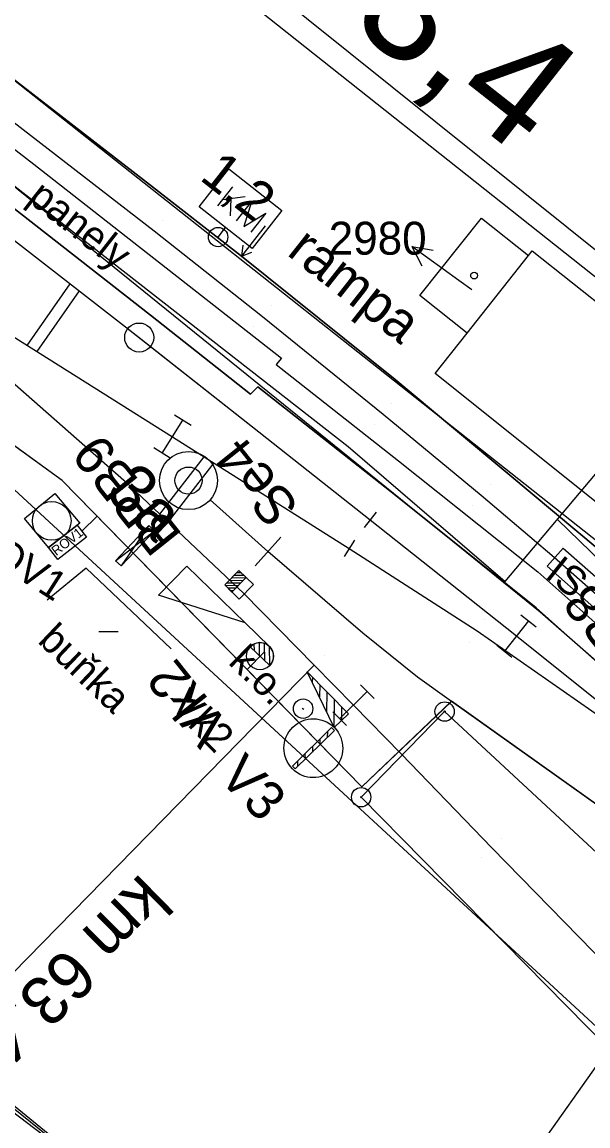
# Model space of a CAD drawing. Extents: x -620475 to -619963, y -1123010 to -1122510.
# Drawn here: x -620299.9 to -620270.7, y -1122722.8 to -1122665.8 of the extents above; entities that cross this region are included whole.
import ezdxf

# ---------------------------------------------------------------- set-up
doc = ezdxf.new("R2010")
doc.units = 0
for name, color, linetype in [('060601_EOV', 7, 'Continuous'), ('060604_ROZVODY_SEE', 7, 'Continuous'), ('CETIN', 7, 'Continuous'), ('HranDP', 7, 'Continuous'), ('Hranice parcel', 7, 'Continuous'), ('Parcelní čísla', 7, 'Continuous'), ('Pop  PČ popisy', 7, 'Continuous'), ('PS 06-14-01_trasa_sdělovací_nové', 7, 'Continuous'), ('SEE', 7, 'Continuous'), ('SSZT', 7, 'Continuous'), ('Vnitřní kresba', 7, 'Continuous'), ('Vrstva 1', 7, 'Continuous'), ('Vrstva 12', 7, 'Continuous'), ('Vrstva 16', 7, 'Continuous'), ('Vrstva 2', 7, 'Continuous'), ('Vrstva 23', 7, 'Continuous'), ('Vrstva 25', 7, 'Continuous'), ('Vrstva 27', 7, 'Continuous'), ('Vrstva 3', 7, 'Continuous'), ('Vrstva 4', 7, 'Continuous'), ('Vrstva 51', 7, 'Continuous'), ('Vrstva 59', 7, 'Continuous'), ('Vrstva 62', 7, 'Continuous'), ('Vrstva 7', 7, 'Continuous'), ('Věcná břemena k části', 7, 'Continuous'), ('Značky bodu BP', 7, 'Continuous'), ('Značky budov', 7, 'Continuous')]:
    doc.layers.add(name, color=color, linetype=linetype)

msp = doc.modelspace()

# ---------------------------------------------------------------- linework, layer by layer
at = {"layer": '060601_EOV'}
msp.add_lwpolyline([(-620235.16, -1122712.242), (-620240.174, -1122718.342), (-620243.025, -1122715.998), (-620248.321, -1122722.765), (-620259.889, -1122713.575), (-620277.713, -1122700.902), (-620282.346, -1122705.302), (-620297.82, -1122689.49), (-620304.222, -1122684.862), (-620310.815, -1122680.061), (-620322.228, -1122672.322), (-620343.182, -1122658.459), (-620368.499, -1122642.897), (-620385.559, -1122631.811)], dxfattribs=at)
at = {"layer": '060604_ROZVODY_SEE'}
msp.add_line((-620296.802, -1122692.105), (-620296.015, -1122691.335), dxfattribs=at)
msp.add_lwpolyline([(-620243.025, -1122715.998), (-620248.321, -1122722.765), (-620259.889, -1122713.575), (-620277.713, -1122700.902), (-620282.346, -1122705.302), (-620297.82, -1122689.49), (-620304.222, -1122684.862), (-620310.815, -1122680.061), (-620316.822, -1122675.988), (-620322.228, -1122672.322), (-620326.634, -1122669.408), (-620343.182, -1122658.459), (-620368.499, -1122642.897), (-620385.559, -1122631.811)], dxfattribs=at)
msp.add_lwpolyline([(-620298.522, -1122692.948), (-620297.044, -1122691.795), (-620296.56, -1122692.415), (-620298.039, -1122693.568)], close=True, dxfattribs=at)
at = {"layer": 'CETIN'}
for points in [[(-620398.075, -1122646.118), (-620362.48, -1122674.84), (-620281.95, -1122736.09)], [(-620281.95, -1122736.09), (-620279.78, -1122731.91), (-620278.12, -1122730.04), (-620275.23, -1122726.8), (-620267.96, -1122716.51), (-620253.8, -1122706.08), (-620234.3, -1122721.82), (-620227.04, -1122727.67)]]:
    msp.add_lwpolyline(points, dxfattribs=at)
at = {"layer": 'HranDP'}
for points in [[(-620296.23, -1122649.3), (-620298.73, -1122654.76), (-620265, -1122681.82), (-620263.22, -1122682.69), (-620260.55, -1122682.94), (-620253.83, -1122686.12), (-620245.73, -1122689.53), (-620242.51, -1122691.82), (-620225.75, -1122705.35), (-620226.24, -1122705.93)], [(-620310.57, -1122708.76), (-620307.94, -1122715.53), (-620278.65, -1122739.48), (-620275.74, -1122741.01)]]:
    msp.add_lwpolyline(points, dxfattribs=at)
at = {"layer": 'Hranice parcel'}
for points in [[(-620296.23, -1122649.3), (-620298.73, -1122654.76), (-620265, -1122681.82), (-620263.22, -1122682.69), (-620260.55, -1122682.94), (-620253.83, -1122686.12), (-620245.73, -1122689.53), (-620242.51, -1122691.82), (-620225.75, -1122705.35), (-620226.24, -1122705.93)], [(-620302.66, -1122666.96), (-620267.81, -1122694.49), (-620266.86, -1122693.31), (-620261.82, -1122686.93), (-620261.22, -1122686.17), (-620299.15, -1122656.1), (-620301.83, -1122654.06), (-620305.28, -1122659.46), (-620299.56, -1122663.58), (-620302.66, -1122666.96)], [(-620264.06, -1122726.18), (-620263.28, -1122725.23), (-620282.38, -1122705.84), (-620278.07, -1122701.42), (-620246.12, -1122731.05)], [(-620310.57, -1122708.76), (-620307.94, -1122715.53), (-620278.65, -1122739.48), (-620275.74, -1122741.01)]]:
    msp.add_lwpolyline(points, dxfattribs=at)
at = {"layer": 'Pop  PČ popisy'}
for p, q in [((-620277.33, -1122679.17), (-620279.758, -1122677.406)), ((-620279.758, -1122677.406), (-620278.653, -1122677.59)), ((-620279.758, -1122677.406), (-620279.242, -1122678.4)), ((-620276.66, -1122679.65), (-620277.33, -1122679.17))]:
    msp.add_line(p, q, dxfattribs=at)
at = {"layer": 'PS 06-14-01_trasa_sdělovací_nové'}
msp.add_lwpolyline([(-620248.321, -1122722.765), (-620259.889, -1122713.575), (-620277.711, -1122700.887), (-620282.346, -1122705.302), (-620297.82, -1122689.49), (-620310.815, -1122680.061), (-620322.228, -1122672.322), (-620343.182, -1122658.459), (-620368.499, -1122642.897), (-620385.559, -1122631.811)], dxfattribs=at)
at = {"layer": 'SEE'}
msp.add_line((-620272.241, -1122691.503), (-620257.327, -1122706.026), dxfattribs=at)
for points in [[(-620340.053, -1122630.257), (-620307.038, -1122645.433), (-620304.995, -1122662.882), (-620304.721, -1122665.223), (-620302.66, -1122666.96), (-620305.446, -1122670.265), (-620283.044, -1122687.742), (-620274.947, -1122694.711), (-620269.357, -1122688.084), (-620267.489, -1122689.555)], [(-620244.518, -1122694.296), (-620246.547, -1122692.66), (-620267.469, -1122718.6), (-620268.222, -1122719.534), (-620284.407, -1122704.62), (-620304.333, -1122686.26), (-620309.55, -1122681.453), (-620327.714, -1122669.483), (-620362.834, -1122646.339), (-620385.658, -1122631.923)]]:
    msp.add_lwpolyline(points, dxfattribs=at)
at = {"layer": 'SSZT'}
msp.add_lwpolyline([(-620386.367, -1122632.734), (-620363.271, -1122647.563), (-620313.966, -1122679.218), (-620306.51, -1122669.289), (-620273.137, -1122696.274), (-620258.422, -1122709.142), (-620248.072, -1122696.094)], dxfattribs=at)
at = {"layer": 'Vnitřní kresba'}
for p, q in [((-620279.35, -1122679.94), (-620276.17, -1122675.94)), ((-620276.17, -1122675.94), (-620273.73, -1122677.87)), ((-620276.91, -1122681.88), (-620273.73, -1122677.87)), ((-620273.73, -1122677.87), (-620273.55, -1122677.64)), ((-620273.55, -1122677.64), (-620261.82, -1122686.93)), ((-620276.91, -1122681.88), (-620279.35, -1122679.94)), ((-620278.56, -1122683.97), (-620276.91, -1122681.88)), ((-620266.86, -1122693.31), (-620278.56, -1122683.97))]:
    msp.add_line(p, q, dxfattribs=at)
at = {"layer": 'Vrstva 1'}
for p, q in [((-620287.398, -1122698.346), (-620288.271, -1122699.248)), ((-620282.346, -1122705.302), (-620288.271, -1122699.248)), ((-620277.713, -1122700.902), (-620278.485, -1122701.635)), ((-620259.889, -1122713.575), (-620277.713, -1122700.902)), ((-620282.346, -1122705.302), (-620278.485, -1122701.635))]:
    msp.add_line(p, q, dxfattribs=at)
for points in [[(-620383.649, -1122629.627), (-620378.269, -1122633.015), (-620362.958, -1122642.66), (-620347.616, -1122652.305), (-620342.456, -1122655.575), (-620322.526, -1122668.083), (-620312.925, -1122674.13), (-620301.163, -1122681.549), (-620292.126, -1122687.227), (-620282.992, -1122692.997), (-620276.394, -1122697.25), (-620266.758, -1122703.956), (-620255.894, -1122712.191)], [(-620322.526, -1122668.083), (-620313.097, -1122674.436), (-620308.214, -1122678.053), (-620306.7, -1122679.227), (-620305.337, -1122680.296), (-620302.152, -1122682.886), (-620294.636, -1122689.472), (-620288.443, -1122695.324), (-620284.812, -1122699.019), (-620282.778, -1122701.089), (-620280.313, -1122703.598), (-620275.628, -1122708.447), (-620262.902, -1122721.469), (-620255.487, -1122728.261), (-620248.439, -1122734.187)], [(-620300.366, -1122670.953), (-620293.063, -1122676.601), (-620287.47, -1122681.018), (-620281.24, -1122686.066), (-620276.174, -1122690.251), (-620272.417, -1122693.451), (-620267.757, -1122697.544), (-620266.519, -1122698.689), (-620262.242, -1122702.65), (-620256.103, -1122708.562), (-620249.907, -1122714.621), (-620245.657, -1122718.815), (-620238.557, -1122725.547), (-620230.199, -1122732.623), (-620229.854, -1122732.906)], [(-620288.271, -1122699.248), (-620297.82, -1122689.49), (-620304.222, -1122684.862), (-620310.815, -1122680.061), (-620311.612, -1122679.521), (-620316.822, -1122675.988)], [(-620300.906, -1122676.615), (-620294.546, -1122681.556), (-620293.844, -1122682.108), (-620287.988, -1122686.712), (-620281.909, -1122691.52), (-620277.852, -1122694.735), (-620274.362, -1122697.517), (-620269.944, -1122701.034), (-620263.761, -1122705.928), (-620255.894, -1122712.191), (-620251.107, -1122715.999), (-620247.589, -1122718.79), (-620245.37, -1122720.556), (-620245.065, -1122720.798), (-620243.16, -1122722.318), (-620236.673, -1122727.474), (-620229.854, -1122732.906), (-620228.705, -1122733.823), (-620228.351, -1122734.106), (-620222.324, -1122738.923), (-620215.936, -1122744.099), (-620211.427, -1122747.773)], [(-620300.906, -1122676.615), (-620294.546, -1122681.556), (-620287.988, -1122686.712), (-620281.909, -1122691.52), (-620277.852, -1122694.735), (-620274.362, -1122697.517), (-620269.944, -1122701.034), (-620263.761, -1122705.928), (-620255.894, -1122712.191), (-620251.107, -1122715.999), (-620247.589, -1122718.79), (-620245.37, -1122720.556), (-620245.065, -1122720.798), (-620243.16, -1122722.318), (-620236.673, -1122727.474), (-620229.854, -1122732.906), (-620228.705, -1122733.823), (-620228.351, -1122734.106), (-620222.324, -1122738.923)], [(-620277.713, -1122700.902), (-620279.474, -1122699.649), (-620282.292, -1122697.371), (-620287.195, -1122693.156)]]:
    msp.add_lwpolyline(points, dxfattribs=at)
at = {"layer": 'Vrstva 12'}
msp.add_line((-620287.336, -1122676.337), (-620288.569, -1122677.912), dxfattribs=at)
for points in [[(-620269.034, -1122691.627), (-620267.487, -1122692.828), (-620266.853, -1122693.319), (-620266.853, -1122693.319), (-620269.034, -1122691.627), (-620269.675, -1122692.369), (-620270.193, -1122692.979), (-620274.695, -1122689.218), (-620280.626, -1122684.271), (-620288.569, -1122677.912), (-620293.461, -1122674.083), (-620303.242, -1122666.538)], [(-620303.242, -1122666.538), (-620293.461, -1122674.083), (-620288.569, -1122677.912), (-620280.626, -1122684.271), (-620274.695, -1122689.218), (-620270.193, -1122692.979), (-620269.675, -1122692.369), (-620269.675, -1122692.369)], [(-620288.497, -1122677.333), (-620288.569, -1122677.912), (-620288.025, -1122677.703)], [(-620299.774, -1122691.456), (-620298.203, -1122690.164), (-620296.914, -1122691.694), (-620298.522, -1122692.948), (-620299.774, -1122691.456)]]:
    msp.add_lwpolyline(points, dxfattribs=at)
at = {"layer": 'Vrstva 16'}
msp.add_lwpolyline([(-620268.767, -1122698.19), (-620269.667, -1122699.332), (-620273.339, -1122696.067), (-620280.591, -1122690.258), (-620287.721, -1122684.651), (-620288.092, -1122685.04), (-620293.259, -1122680.96), (-620301.343, -1122674.65), (-620308.503, -1122669.28), (-620315.629, -1122664.052), (-620319.501, -1122661.293), (-620318.339, -1122659.55), (-620317.166, -1122660.468), (-620313.424, -1122663.148), (-620313.111, -1122662.768), (-620309.78, -1122665.216), (-620304.891, -1122668.836), (-620299.292, -1122673.151), (-620286.498, -1122683.168), (-620286.771, -1122683.508), (-620280.456, -1122688.482), (-620273.255, -1122694.212), (-620268.767, -1122698.19)], dxfattribs=at)
at = {"layer": 'Vrstva 2'}
for p, q in [((-620290.179, -1122690.492), (-620287.195, -1122693.156)), ((-620281.598, -1122691.128), (-620282.22, -1122691.912)), ((-620287.861, -1122693.902), (-620286.529, -1122692.41)), ((-620282.721, -1122692.577), (-620283.263, -1122693.417)), ((-620288.34, -1122694.521), (-620289.083, -1122694.53)), ((-620288.43, -1122694.39), (-620288.953, -1122694.397)), ((-620288.563, -1122694.261), (-620288.824, -1122694.264)), ((-620288.729, -1122694.919), (-620289.383, -1122694.928)), ((-620288.6, -1122694.786), (-620289.342, -1122694.796)), ((-620288.859, -1122695.052), (-620289.25, -1122695.057)), ((-620288.47, -1122694.653), (-620289.212, -1122694.663)), ((-620288.988, -1122695.185), (-620289.117, -1122695.187)), ((-620288.369, -1122696.837), (-620287.116, -1122698.058)), ((-620287.917, -1122697.934), (-620287.913, -1122698.259)), ((-620287.655, -1122697.863), (-620287.647, -1122698.518)), ((-620287.393, -1122697.895), (-620287.381, -1122698.777)), ((-620287.128, -1122698.047), (-620287.116, -1122699.036)), ((-620287.103, -1122699.048), (-620288.106, -1122698.071))]:
    msp.add_line(p, q, dxfattribs=at)
for points in [[(-620281.909, -1122691.52), (-620277.852, -1122694.735), (-620274.362, -1122697.517), (-620269.944, -1122701.034), (-620263.761, -1122705.928), (-620255.894, -1122712.191)], [(-620282.992, -1122692.997), (-620276.394, -1122697.25), (-620266.758, -1122703.956), (-620255.894, -1122712.191)]]:
    msp.add_lwpolyline(points, dxfattribs=at)
for points in [[(-620291.376, -1122693.905), (-620288.369, -1122696.837), (-620292.842, -1122695.409)], [(-620289.052, -1122695.25), (-620289.428, -1122694.884), (-620288.695, -1122694.132), (-620288.319, -1122694.498)], [(-620289.052, -1122695.25), (-620289.428, -1122694.884), (-620288.695, -1122694.132), (-620288.319, -1122694.498)], [(-620288.676, -1122695.617), (-620289.428, -1122694.884), (-620288.695, -1122694.132), (-620287.943, -1122694.865)]]:
    msp.add_lwpolyline(points, close=True, dxfattribs=at)
for centre, radius in [((-620291.298, -1122689.493), 1.5), ((-620291.298, -1122689.493), 0.7), ((-620287.605, -1122698.559), 0.7)]:
    msp.add_circle(centre, radius, dxfattribs=at)
msp.add_arc((-620287.605, -1122698.559), 0.7, 315.7256, 135.731, dxfattribs=at)
at = {"layer": 'Vrstva 23'}
msp.add_lwpolyline([(-620292.2, -1122698.187), (-620296.588, -1122694.01), (-620298.602, -1122695.675)], dxfattribs=at)
at = {"layer": 'Vrstva 25'}
msp.add_circle((-620298.364, -1122691.573), 1, dxfattribs=at)
at = {"layer": 'Vrstva 27'}
msp.add_line((-620285.423, -1122701.244), (-620285.337, -1122701.296), dxfattribs=at)
msp.add_circle((-620285.38, -1122701.27), 0.5, dxfattribs=at)
at = {"layer": 'Vrstva 3'}
for p, q in [((-620292.66, -1122688.072), (-620291.592, -1122686.382)), ((-620291.169, -1122686.649), (-620292.015, -1122686.115)), ((-620292.237, -1122688.339), (-620293.083, -1122687.805)), ((-620273.739, -1122696.735), (-620274.985, -1122698.299)), ((-620273.739, -1122696.735), (-620274.985, -1122698.299)), ((-620274.13, -1122696.423), (-620273.348, -1122697.046)), ((-620274.13, -1122696.423), (-620273.348, -1122697.046)), ((-620275.376, -1122697.988), (-620274.594, -1122698.611)), ((-620275.376, -1122697.988), (-620274.594, -1122698.611)), ((-620284.812, -1122699.019), (-620302.722, -1122717.317)), ((-620284.897, -1122699.646), (-620284.906, -1122699.909)), ((-620284.518, -1122700.031), (-620284.538, -1122700.665)), ((-620282.415, -1122700.032), (-620281.714, -1122700.745)), ((-620284.147, -1122700.409), (-620284.163, -1122701.435)), ((-620283.775, -1122700.788), (-620283.788, -1122702.214)), ((-620282.065, -1122700.388), (-620283.491, -1122701.79)), ((-620283.842, -1122701.433), (-620283.141, -1122702.146)), ((-620283.396, -1122701.173), (-620283.402, -1122701.887)), ((-620284.127, -1122702.459), (-620284.135, -1122702.759)), ((-620284.512, -1122702.837), (-620284.515, -1122703.131)), ((-620285.282, -1122703.594), (-620285.278, -1122703.881)), ((-620284.897, -1122703.216), (-620284.9, -1122703.51)), ((-620285.662, -1122703.967), (-620285.663, -1122704.26))]:
    msp.add_line(p, q, dxfattribs=at)
for points in [[(-620285.169, -1122699.369), (-620283.042, -1122701.534), (-620283.768, -1122702.246)], [(-620285.932, -1122704.232), (-620285.786, -1122704.38), (-620283.763, -1122702.394), (-620283.909, -1122702.245)]]:
    msp.add_lwpolyline(points, close=True, dxfattribs=at)
msp.add_ellipse((-620284.849, -1122703.312), major_axis=(1.083, 1.064), ratio=0.999996, dxfattribs=at)
at = {"layer": 'Vrstva 4'}
msp.add_lwpolyline([(-620271.94, -1122692.987), (-620267.429, -1122696.942), (-620268.266, -1122697.909), (-620272.78, -1122693.919), (-620271.94, -1122692.987)], dxfattribs=at)
at = {"layer": 'Vrstva 51'}
msp.add_lwpolyline([(-620319.501, -1122661.293), (-620315.629, -1122664.052), (-620308.503, -1122669.28), (-620301.343, -1122674.65), (-620293.259, -1122680.96), (-620288.092, -1122685.04), (-620287.721, -1122684.651), (-620280.591, -1122690.258), (-620273.339, -1122696.067), (-620269.667, -1122699.332)], dxfattribs=at)
at = {"layer": 'Vrstva 59'}
msp.add_line((-620295.937, -1122697.294), (-620294.937, -1122697.294), dxfattribs=at)
at = {"layer": 'Vrstva 62'}
for p, q in [((-620292.625, -1122676.047), (-620292.625, -1122676.047)), ((-620293.501, -1122677.156), (-620293.501, -1122677.156)), ((-620287.021, -1122680.479), (-620287.021, -1122680.479)), ((-620287.92, -1122681.558), (-620287.92, -1122681.558)), ((-620280.798, -1122685.52), (-620280.798, -1122685.52)), ((-620291.747, -1122686.622), (-620291.747, -1122686.622)), ((-620281.682, -1122686.611), (-620281.682, -1122686.611)), ((-620292.505, -1122687.832), (-620292.505, -1122687.832)), ((-620294.186, -1122688.929), (-620294.186, -1122688.929)), ((-620295.086, -1122690.014), (-620295.086, -1122690.014)), ((-620275.718, -1122689.718), (-620275.718, -1122689.718)), ((-620276.63, -1122690.785), (-620276.63, -1122690.785)), ((-620282.605, -1122692.402), (-620282.605, -1122692.402)), ((-620271.958, -1122692.911), (-620271.958, -1122692.911)), ((-620283.378, -1122693.592), (-620283.378, -1122693.592)), ((-620272.875, -1122693.991), (-620272.875, -1122693.991)), ((-620287.958, -1122694.78), (-620287.958, -1122694.78)), ((-620288.927, -1122695.869), (-620288.927, -1122695.869)), ((-620276.009, -1122696.653), (-620276.009, -1122696.653)), ((-620276.779, -1122697.848), (-620276.779, -1122697.848)), ((-620284.298, -1122698.515), (-620284.298, -1122698.515)), ((-620285.326, -1122699.523), (-620285.326, -1122699.523)), ((-620282.299, -1122700.556), (-620282.299, -1122700.556)), ((-620283.256, -1122701.623), (-620283.256, -1122701.623)), ((-620279.845, -1122703.061), (-620279.845, -1122703.061)), ((-620280.78, -1122704.135), (-620280.78, -1122704.135)), ((-620275.114, -1122707.965), (-620275.114, -1122707.965)), ((-620276.142, -1122708.929), (-620276.142, -1122708.929))]:
    msp.add_line(p, q, dxfattribs=at)
at = {"layer": 'Vrstva 7'}
for p, q in [((-620289.031, -1122674.335), (-620289.802, -1122675.315)), ((-620288.375, -1122674.851), (-620289.547, -1122674.991)), ((-620289.12, -1122674.94), (-620289.146, -1122675.831)), ((-620289.809, -1122676.889), (-620289.731, -1122676.951)), ((-620289.77, -1122676.92), (-620289.385, -1122676.43)), ((-620299.627, -1122682.514), (-620297.403, -1122679.337)), ((-620299.118, -1122682.834), (-620296.928, -1122679.705)), ((-620298.228, -1122681.039), (-620298.228, -1122681.039)), ((-620292.784, -1122691.222), (-620290.487, -1122688.263)), ((-620292.346, -1122691.636), (-620289.977, -1122688.585)), ((-620291.393, -1122689.919), (-620291.393, -1122689.919)), ((-620295.068, -1122693.629), (-620293.058, -1122692.089))]:
    msp.add_line(p, q, dxfattribs=at)
msp.add_lwpolyline([(-620290.754, -1122675.354), (-620289.22, -1122673.402), (-620286.478, -1122675.557), (-620288.012, -1122677.509)], close=True, dxfattribs=at)
for points in [[(-620288.822, -1122676.086), (-620288.051, -1122675.105), (-620288.443, -1122676.383), (-620287.302, -1122675.694), (-620288.073, -1122676.674)], [(-620293.349, -1122691.814), (-620294.777, -1122693.904), (-620295.068, -1122693.629), (-620293.349, -1122691.814), (-620293.058, -1122692.089), (-620294.777, -1122693.904)]]:
    msp.add_lwpolyline(points, dxfattribs=at)
for centre, radius in [((-620289.77, -1122676.92), 0.5), ((-620293.844, -1122682.108), 0.75), ((-620293.844, -1122682.108), 0.75)]:
    msp.add_circle(centre, radius, dxfattribs=at)
at = {"layer": 'Věcná břemena k části'}
msp.add_lwpolyline([(-620408.148, -1122657.633), (-620389.78, -1122673.21), (-620362.07, -1122697.07), (-620350.79, -1122712.11), (-620329.91, -1122699.79), (-620318.75, -1122707.75), (-620310.23, -1122716.49), (-620285.9, -1122736.09), (-620287.87, -1122738.92), (-620280.66, -1122744.45), (-620246.32, -1122763.41), (-620202.66, -1122784.39), (-620201.79, -1122782.59), (-620245.45, -1122761.61), (-620279.7, -1122742.7), (-620285.15, -1122738.52), (-620283.23, -1122735.73), (-620308.89, -1122715.01), (-620317.45, -1122706.23), (-620329.81, -1122697.41), (-620350.27, -1122709.47), (-620360.61, -1122695.69), (-620388.48, -1122671.69), (-620406.835, -1122656.132)], dxfattribs=at)
at = {"layer": 'Značky bodu BP'}
for centre, radius in [((-620278.07, -1122701.42), 0.5), ((-620278.07, -1122701.42), 0.0303), ((-620282.38, -1122705.84), 0.5), ((-620282.38, -1122705.84), 0.0303)]:
    msp.add_circle(centre, radius, dxfattribs=at)
at = {"layer": 'Značky budov'}
msp.add_circle((-620276.547, -1122678.909), 0.175, dxfattribs=at)

# ---------------------------------------------------------------- texts
at = {"layer": '060604_ROZVODY_SEE'}
msp.add_text('ROV1', height=0.5, rotation=37.9489, dxfattribs=at).set_placement((-620298.131, -1122693.398))
at = {"layer": 'Parcelní čísla'}
msp.add_text('2980', height=1.7, dxfattribs=at).set_placement((-620284.057, -1122677.83))
at = {"layer": 'Vrstva 1'}
msp.add_text('3a', height=2.5, rotation=316.6216, dxfattribs=at).set_placement((-620295.691, -1122690.195))
at = {"layer": 'Vrstva 12'}
for s, rotation, p in [('1,2', 321.9495, (-620290.78, -1122673.923)), ('rampa', 321.7315, (-620286.274, -1122677.804))]:
    msp.add_text(s, height=2, rotation=rotation, dxfattribs=at).set_placement(p)
at = {"layer": 'Vrstva 16'}
msp.add_text('panely', height=1.5, rotation=321.941, dxfattribs=at).set_placement((-620299.672, -1122675.04))
at = {"layer": 'Vrstva 23'}
msp.add_text('buňka', height=1.5, rotation=316.4112, dxfattribs=at).set_placement((-620299.139, -1122697.822))
at = {"layer": 'Vrstva 25'}
msp.add_text('OV1', height=1.5, rotation=327.3569, dxfattribs=at).set_placement((-620301.598, -1122693.603))
at = {"layer": 'Vrstva 27'}
for s, height, rotation, p in [('k.o.', 1.5, 315.6422, (-620289.294, -1122698.925)), ('V3', 2, 314.0427, (-620289.814, -1122704.853))]:
    msp.add_text(s, height=height, rotation=rotation, dxfattribs=at).set_placement(p)
at = {"layer": 'Vrstva 3'}
for s, height, rotation, p in [('BPB9', 2, 128.542, (-620291.576, -1122692.306)), ('Se4', 2, 128.542, (-620285.524, -1122690.835)), ('IS', 1.5, 321.4781, (-620272.94, -1122694.455)), ('BPB8', 2, 128.542, (-620266.236, -1122699.997)), ('Vk2', 2, 128.542, (-620289.121, -1122702.185)), ('Vk2', 1.5, 314.4932, (-620292.324, -1122701.175)), ('km 63,419', 2.5, 224.4932, (-620293.75, -1122709.718))]:
    msp.add_text(s, height=height, rotation=rotation, dxfattribs=at).set_placement(p)
at = {"layer": 'Vrstva 4'}
msp.add_text('Přechod', height=1.5, rotation=226.218, dxfattribs=at).set_placement((-620267.27, -1122721.279))
at = {"layer": 'Vrstva 7'}
msp.add_text('63,4', height=6, rotation=321.8255, dxfattribs=at).set_placement((-620286.609, -1122663.084))

doc.saveas('drawing.dxf')
